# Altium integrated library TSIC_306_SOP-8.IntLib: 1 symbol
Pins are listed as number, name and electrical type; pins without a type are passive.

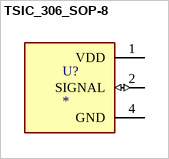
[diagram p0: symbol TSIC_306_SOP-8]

## TSIC_306_SOP-8
designator U?
SENSOR, TEMP, DIGITAL, 0.3DEG C, SOP-8; SVHC: No SVHC (20-Jun-2013); MF: IST; MP: TSIC 306 SOP-8
footprint SOIC127P602X173-8N
pins: 1 VDD (power), 2 SIGNAL (io), 4 GND (power)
